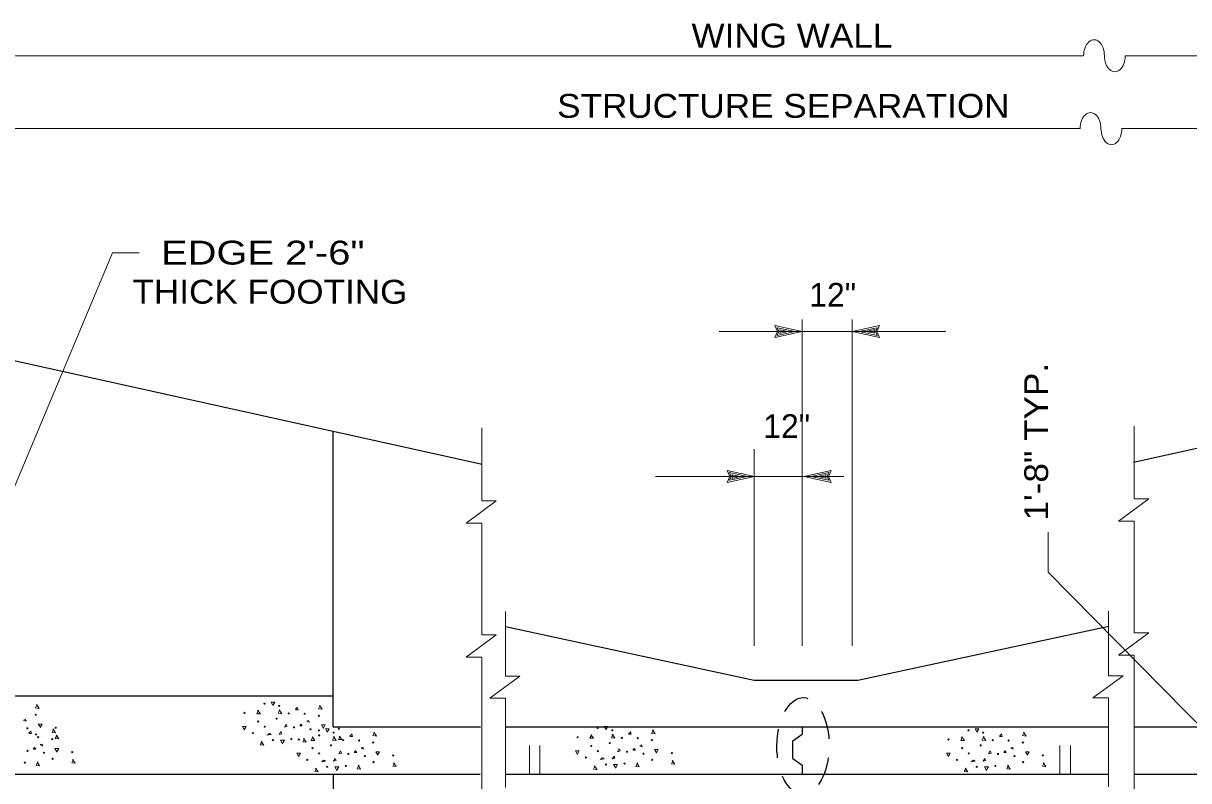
# Model space of a CAD drawing. Extents: x -22.3 to 19.7, y -11.8 to 18.2.
# Drawn here: x -0.65 to 5.45, y 2.35 to 6.32 of the extents above; entities that cross this region are included whole.
import ezdxf
from ezdxf.enums import TextEntityAlignment as Align

# ---------------------------------------------------------------- set-up
doc = ezdxf.new("R2010")
doc.units = 0
doc.header["$LTSCALE"] = 0.05
doc.linetypes.add('MEDIUM_DASHED', pattern=[4.5, 3, -1.5])
doc.layers.add('1', color=7, linetype='Continuous', lineweight=13)
doc.layers.add('2', color=7, linetype='Continuous', lineweight=13)

msp = doc.modelspace()

# ---------------------------------------------------------------- linework, layer by layer
at = {"layer": '1'}
for p, q in [((-1.02142, 6.14831), (4.89858, 6.14831)), ((5.11858, 6.14831), (7.85258, 6.14831)), ((-1.02142, 5.76631), (4.88358, 5.76631)), ((5.09858, 5.76631), (7.85258, 5.76631)), ((-0.18742, 5.11631), (-0.04642, 5.11631)), ((3.42658, 3.05731), (3.42658, 4.76731)), ((3.68758, 3.05731), (3.68758, 4.76731)), ((3.42658, 4.70331), (3.28258, 4.73431)), ((3.42658, 4.70331), (3.28258, 4.67231)), ((3.38958, 4.70331), (3.29558, 4.72331)), ((3.30458, 4.70331), (3.29558, 4.72331)), ((3.38958, 4.70331), (3.29558, 4.68331)), ((3.29558, 4.68331), (3.30458, 4.70331)), ((3.35358, 4.70331), (3.30858, 4.71231)), ((3.31258, 4.70331), (3.30858, 4.71231)), ((3.35358, 4.70331), (3.30858, 4.69331)), ((3.30858, 4.69331), (3.31258, 4.70331)), ((3.68758, 4.70331), (3.83158, 4.73431)), ((3.68758, 4.70331), (3.83158, 4.67231)), ((3.72458, 4.70331), (3.81858, 4.72331)), ((3.72458, 4.70331), (3.81858, 4.68331)), ((3.76058, 4.70331), (3.80558, 4.71331)), ((3.76058, 4.70331), (3.80558, 4.69431)), ((3.80558, 4.71331), (3.80158, 4.70331)), ((3.80158, 4.70331), (3.80558, 4.69431)), ((3.81858, 4.72331), (3.80958, 4.70331)), ((3.80958, 4.70331), (3.81858, 4.68331)), ((1.74758, 3.81631), (1.74758, 4.19831)), ((5.16558, 3.82631), (5.16558, 4.20831)), ((3.17458, 3.05731), (3.17458, 4.08731)), ((3.17658, 3.94431), (3.03258, 3.97531)), ((3.43458, 3.94431), (3.57858, 3.97531)), ((3.17658, 3.94431), (3.03258, 3.91331)), ((3.13958, 3.94431), (3.04558, 3.96431)), ((3.05458, 3.94431), (3.04558, 3.96431)), ((3.13958, 3.94431), (3.04558, 3.92431)), ((3.04558, 3.92431), (3.05458, 3.94431)), ((3.10358, 3.94431), (3.05858, 3.95331)), ((3.06258, 3.94431), (3.05858, 3.95331)), ((3.10358, 3.94431), (3.05858, 3.93431)), ((3.05858, 3.93431), (3.06258, 3.94431)), ((3.43458, 3.94431), (3.57858, 3.91331)), ((3.43458, 3.94431), (3.64458, 3.94431)), ((3.47158, 3.94431), (3.56558, 3.96431)), ((3.47158, 3.94431), (3.56558, 3.92431)), ((3.50758, 3.94431), (3.55258, 3.95431)), ((3.50758, 3.94431), (3.55258, 3.93531)), ((3.55258, 3.95431), (3.54858, 3.94431)), ((3.54858, 3.94431), (3.55258, 3.93531)), ((3.56558, 3.96431), (3.55658, 3.94431)), ((3.55658, 3.94431), (3.56558, 3.92431)), ((1.66558, 3.70031), (1.82358, 3.81631)), ((1.74758, 3.81631), (1.82358, 3.81631)), ((5.08358, 3.71031), (5.24158, 3.82631)), ((5.16558, 3.82631), (5.24158, 3.82631)), ((1.66558, 3.70031), (1.74758, 3.70031)), ((1.74758, 3.11431), (1.74758, 3.70031)), ((5.08358, 3.71031), (5.16558, 3.71031)), ((5.16558, 3.12431), (5.16558, 3.71031)), ((1.87158, 2.89831), (1.87158, 3.23731)), ((5.03158, 2.90031), (5.03158, 3.23931)), ((1.66558, 2.99831), (1.82358, 3.11431)), ((1.74758, 3.11431), (1.82358, 3.11431)), ((5.08358, 3.00831), (5.24158, 3.12431)), ((5.16558, 3.12431), (5.24158, 3.12431)), ((1.66558, 2.99831), (1.74758, 2.99831)), ((1.74758, 2.17131), (1.74758, 2.99831)), ((5.08358, 3.00831), (5.16558, 3.00831)), ((5.16558, 2.18131), (5.16558, 3.00831)), ((1.78958, 2.78231), (1.94758, 2.89831)), ((1.87158, 2.89831), (1.94758, 2.89831)), ((4.94958, 2.78431), (5.10758, 2.90031)), ((5.03158, 2.90031), (5.10758, 2.90031)), ((1.78958, 2.78231), (1.87158, 2.78231)), ((1.87158, 2.31531), (1.87158, 2.78231)), ((4.94958, 2.78431), (5.03158, 2.78431)), ((5.03158, 2.31731), (5.03158, 2.78431))]:
    msp.add_line(p, q, dxfattribs=at)
at = {"layer": '1', "lineweight": 25}
for p, q in [((-1.02142, 4.62231), (1.75058, 4.00831)), ((5.16258, 4.01931), (7.85058, 4.61031)), ((0.96858, 2.63231), (0.96858, 4.18131)), ((1.87258, 3.15731), (3.17458, 2.87631)), ((3.71858, 2.87631), (5.03258, 3.15931)), ((3.17458, 2.87631), (3.71858, 2.87631)), ((-1.02142, 2.79431), (0.96858, 2.79431)), ((0.96858, 2.63231), (1.74058, 2.63231)), ((1.87158, 2.63231), (5.03158, 2.63231)), ((3.42658, 2.62831), (3.42658, 2.59431)), ((5.16558, 2.63231), (5.90958, 2.63231)), ((3.37658, 2.46731), (3.42658, 2.43231)), ((-3.04142, 2.38431), (1.73958, 2.38431)), ((0.96858, 2.38431), (0.96858, 1.77531)), ((1.87158, 2.38431), (5.03158, 2.38431)), ((3.42658, 2.43231), (3.42658, 2.38331)), ((5.16558, 2.38431), (9.28558, 2.38431))]:
    msp.add_line(p, q, dxfattribs=at)
at = {"layer": '1', "linetype": 'MEDIUM_DASHED'}
for p, q in [((1.99858, 2.38431), (1.99858, 2.63231)), ((2.05158, 2.38431), (2.05158, 2.63231)), ((4.77658, 2.38431), (4.77658, 2.63231)), ((4.83158, 2.38431), (4.83158, 2.63231))]:
    msp.add_line(p, q, dxfattribs=at)
at = {"layer": '1'}
for points in [[(-0.18742, 5.11631), (-1.17742, 2.75631), (-1.15042, 2.90131)], [(2.99158, 4.70331), (3.42658, 4.70331), (3.68758, 4.70331), (4.17858, 4.70331)], [(3.28258, 4.67231), (3.29658, 4.70331), (3.28258, 4.73431)], [(3.83158, 4.73431), (3.81758, 4.70331), (3.83158, 4.67231)], [(3.03258, 3.91331), (3.04658, 3.94431), (3.03258, 3.97531)], [(3.57858, 3.97531), (3.56458, 3.94431), (3.57858, 3.91331)], [(2.65858, 3.94431), (3.17658, 3.94431), (3.43458, 3.94431)], [(5.55658, 2.58831), (4.71458, 3.44231), (4.71458, 3.65231)]]:
    msp.add_lwpolyline(points, dxfattribs=at)
at = {"layer": '1', "lineweight": 25}
msp.add_lwpolyline([(3.37658, 2.46731), (3.37658, 2.55931), (3.42658, 2.59431)], dxfattribs=at)
at = {"layer": '1'}
for centre, major_axis in [((4.95508, 6.14831), (0, -0.084)), ((5.06408, 6.14831), (0, 0.084)), ((4.93708, 5.76631), (0, -0.084)), ((5.04608, 5.76631), (0, 0.084))]:
    msp.add_ellipse(centre, major_axis=major_axis, ratio=0.648782, start_param=1.5707963, end_param=4.712389, dxfattribs=at)
at = {"layer": '1', "linetype": 'MEDIUM_DASHED', "lineweight": 25}
msp.add_ellipse((3.43058, 2.53231), major_axis=(-0.002, -0.253), ratio=0.540911, dxfattribs=at)
at = {"layer": '2'}
for p, q in [((0.77158, 2.72431), (0.78158, 2.73331)), ((-0.62442, 2.60131), (-0.61442, 2.61031)), ((1.05658, 2.58431), (1.06658, 2.59331)), ((2.51658, 2.59631), (2.52658, 2.60531)), ((4.45958, 2.58431), (4.46958, 2.59331))]:
    msp.add_line(p, q, dxfattribs=at)
for points in [[(-0.58142, 2.74931), (-0.59042, 2.73131), (-0.57142, 2.72931), (-0.58542, 2.74931)], [(0.65358, 2.74631), (0.64458, 2.76231), (0.66358, 2.76231), (0.65358, 2.74431)], [(0.57858, 2.71931), (0.56958, 2.70131), (0.58858, 2.70031), (0.57358, 2.71931)], [(0.69058, 2.72131), (0.68158, 2.70331), (0.69958, 2.70131), (0.68658, 2.72131)], [(0.78158, 2.73531), (0.78558, 2.72131), (0.77158, 2.72131)], [(0.90158, 2.74431), (0.89258, 2.72631), (0.91158, 2.72431), (0.89758, 2.74431)], [(-0.65242, 2.66731), (-0.64342, 2.67031), (-0.63942, 2.66131), (-0.65242, 2.66531)], [(-0.56642, 2.63231), (-0.57542, 2.64731), (-0.55542, 2.64731), (-0.56642, 2.62831)], [(0.50258, 2.61931), (0.49358, 2.63431), (0.51358, 2.63431), (0.50258, 2.61631)], [(0.79458, 2.63831), (0.80058, 2.64731), (0.80758, 2.63831), (0.79658, 2.63831)], [(0.83058, 2.66231), (0.83958, 2.66531), (0.84358, 2.65631), (0.83058, 2.66031)], [(0.91658, 2.62731), (0.90758, 2.64231), (0.92758, 2.64231), (0.91658, 2.62331)], [(2.39858, 2.61831), (2.38958, 2.63431), (2.40858, 2.63431), (2.39858, 2.61631)], [(-0.61442, 2.61231), (-0.61042, 2.59831), (-0.62442, 2.59831)], [(-0.49442, 2.62131), (-0.50342, 2.60331), (-0.48442, 2.60131), (-0.49842, 2.62131)], [(-0.47742, 2.58931), (-0.48642, 2.57131), (-0.46842, 2.57031), (-0.48242, 2.58931)], [(0.62658, 2.59231), (0.63558, 2.59831), (0.64458, 2.59231), (0.62258, 2.58931)], [(0.81858, 2.57131), (0.80958, 2.55331), (0.82758, 2.55131), (0.81458, 2.57131)], [(0.86358, 2.57931), (0.85458, 2.56131), (0.87358, 2.56031), (0.85858, 2.57931)], [(0.93858, 2.60631), (0.92958, 2.62231), (0.94858, 2.62231), (0.93858, 2.60431)], [(0.97558, 2.58131), (0.96658, 2.56331), (0.98458, 2.56131), (0.97158, 2.58131)], [(1.00558, 2.58431), (0.99658, 2.56631), (1.01458, 2.56531), (1.00058, 2.58431)], [(1.06658, 2.59531), (1.07058, 2.58131), (1.05658, 2.58131)], [(1.18658, 2.60431), (1.17758, 2.58631), (1.19658, 2.58431), (1.18258, 2.60431)], [(2.32358, 2.59131), (2.31458, 2.57331), (2.33358, 2.57231), (2.31858, 2.59131)], [(2.43558, 2.59331), (2.42658, 2.57531), (2.44458, 2.57331), (2.43158, 2.59331)], [(2.52658, 2.60731), (2.53058, 2.59331), (2.51658, 2.59331)], [(2.64658, 2.61631), (2.63758, 2.59831), (2.65658, 2.59631), (2.64258, 2.61631)], [(4.26658, 2.57931), (4.25758, 2.56131), (4.27658, 2.56031), (4.26158, 2.57931)], [(4.34158, 2.60631), (4.33258, 2.62231), (4.35158, 2.62231), (4.34158, 2.60431)], [(4.37858, 2.58131), (4.36958, 2.56331), (4.38758, 2.56131), (4.37458, 2.58131)], [(4.46958, 2.59531), (4.47358, 2.58131), (4.45958, 2.58131)], [(4.58958, 2.60431), (4.58058, 2.58631), (4.59958, 2.58431), (4.58558, 2.60431)], [(-0.60142, 2.51531), (-0.59542, 2.52431), (-0.58842, 2.51531), (-0.59942, 2.51531)], [(-0.56542, 2.53931), (-0.55642, 2.54231), (-0.55242, 2.53331), (-0.56542, 2.53731)], [(-0.47942, 2.50431), (-0.48842, 2.51931), (-0.46842, 2.51931), (-0.47942, 2.50031)], [(0.59658, 2.55631), (0.58758, 2.53831), (0.60658, 2.53631), (0.59158, 2.55631)], [(0.70258, 2.54731), (0.69358, 2.56231), (0.71358, 2.56231), (0.70258, 2.54331)], [(1.07958, 2.49831), (1.08558, 2.50731), (1.09258, 2.49831), (1.08158, 2.49831)], [(1.11558, 2.52231), (1.12458, 2.52531), (1.12858, 2.51631), (1.11558, 2.52031)], [(2.24758, 2.49131), (2.23858, 2.50631), (2.25858, 2.50631), (2.24758, 2.48831)], [(2.53958, 2.51031), (2.54558, 2.51931), (2.55258, 2.51031), (2.54158, 2.51031)], [(2.57558, 2.53431), (2.58458, 2.53731), (2.58858, 2.52831), (2.57558, 2.53231)], [(2.66158, 2.49931), (2.65258, 2.51431), (2.67258, 2.51431), (2.66158, 2.49531)], [(4.48258, 2.49831), (4.48858, 2.50731), (4.49558, 2.49831), (4.48458, 2.49831)], [(4.51858, 2.52231), (4.52758, 2.52531), (4.53158, 2.51631), (4.51858, 2.52031)], [(-0.57742, 2.44831), (-0.58642, 2.43031), (-0.56842, 2.42831), (-0.58142, 2.44831)], [(-0.39042, 2.46131), (-0.39942, 2.44331), (-0.38142, 2.44231), (-0.39542, 2.46131)], [(0.78758, 2.47931), (0.77858, 2.49431), (0.79858, 2.49431), (0.78758, 2.47631)], [(0.91158, 2.45231), (0.92058, 2.45831), (0.92958, 2.45231), (0.90758, 2.44931)], [(1.20158, 2.48731), (1.19258, 2.50231), (1.21258, 2.50231), (1.20158, 2.48331)], [(1.29058, 2.44431), (1.28158, 2.42631), (1.29958, 2.42531), (1.28558, 2.44431)], [(2.37158, 2.46431), (2.38058, 2.47031), (2.38958, 2.46431), (2.36758, 2.46131)], [(2.56358, 2.44331), (2.55458, 2.42531), (2.57258, 2.42331), (2.55958, 2.44331)], [(2.75058, 2.45631), (2.74158, 2.43831), (2.75958, 2.43731), (2.74558, 2.45631)], [(4.19058, 2.47931), (4.18158, 2.49431), (4.20158, 2.49431), (4.19058, 2.47631)], [(4.31458, 2.45231), (4.32358, 2.45831), (4.33258, 2.45231), (4.31058, 2.44931)], [(4.60458, 2.48731), (4.59558, 2.50231), (4.61558, 2.50231), (4.60458, 2.48331)], [(4.69358, 2.44431), (4.68458, 2.42631), (4.70258, 2.42531), (4.68858, 2.44431)], [(0.88158, 2.41631), (0.87258, 2.39831), (0.89158, 2.39631), (0.87658, 2.41631)], [(0.98758, 2.40731), (0.97858, 2.42231), (0.99858, 2.42231), (0.98758, 2.40331)], [(1.10358, 2.43131), (1.09458, 2.41331), (1.11258, 2.41131), (1.09958, 2.43131)], [(2.34158, 2.42831), (2.33258, 2.41031), (2.35158, 2.40831), (2.33658, 2.42831)], [(2.44758, 2.41931), (2.43858, 2.43431), (2.45858, 2.43431), (2.44758, 2.41531)], [(4.28458, 2.41631), (4.27558, 2.39831), (4.29458, 2.39631), (4.27958, 2.41631)], [(4.39058, 2.40731), (4.38158, 2.42231), (4.40158, 2.42231), (4.39058, 2.40331)], [(4.50658, 2.43131), (4.49758, 2.41331), (4.51558, 2.41131), (4.50258, 2.43131)]]:
    msp.add_lwpolyline(points, dxfattribs=at)
for points in [[(0.71358, 2.63031), (0.72258, 2.64731), (0.72758, 2.63531)], [(0.68658, 2.59231), (0.69558, 2.60731), (0.69958, 2.59631)], [(0.99858, 2.49031), (1.00758, 2.50731), (1.01258, 2.49531)], [(2.45858, 2.50231), (2.46758, 2.51931), (2.47258, 2.50731)], [(4.40158, 2.49031), (4.41058, 2.50731), (4.41558, 2.49531)], [(0.97158, 2.45231), (0.98058, 2.46731), (0.98458, 2.45631)], [(2.43158, 2.46431), (2.44058, 2.47931), (2.44458, 2.46831)], [(4.37458, 2.45231), (4.38358, 2.46731), (4.38758, 2.45631)]]:
    msp.add_lwpolyline(points, close=True, dxfattribs=at)
for centre in [(0.60953, 2.75414), (-0.58907, 2.69569), (0.50468, 2.70599), (0.68648, 2.74199), (0.73643, 2.70284), (0.81968, 2.70104), (0.89393, 2.69069), (-0.63272, 2.62459), (-0.48422, 2.62774), (0.57623, 2.66054), (0.61088, 2.63309), (0.67298, 2.67539), (0.76388, 2.62994), (0.99878, 2.62274), (2.35453, 2.62614), (-0.58727, 2.59264), (-0.57632, 2.57804), (-0.50207, 2.56769), (0.54878, 2.59979), (0.65318, 2.56334), (0.75038, 2.56784), (0.78968, 2.56599), (0.85028, 2.61959), (0.89453, 2.61414), (0.89573, 2.58764), (0.97148, 2.60199), (1.02143, 2.56284), (2.24968, 2.57799), (2.43148, 2.61399), (2.48143, 2.57484), (2.56468, 2.57304), (2.63893, 2.56269), (4.19268, 2.56599), (4.29753, 2.61414), (4.37448, 2.60199), (4.42443, 2.56284), (-0.63212, 2.50694), (0.86123, 2.52054), (0.95798, 2.53539), (1.10468, 2.56104), (1.17893, 2.55069), (2.32123, 2.53254), (2.35588, 2.50509), (2.41798, 2.54739), (2.50888, 2.50194), (4.26423, 2.52054), (4.36098, 2.53539), (4.50768, 2.56104), (4.58193, 2.55069), (-0.64562, 2.44484), (-0.54572, 2.49659), (-0.50027, 2.46464), (-0.39722, 2.49974), (0.83378, 2.45979), (0.89588, 2.49309), (1.04888, 2.48994), (1.13528, 2.47959), (1.18073, 2.44764), (1.28378, 2.48274), (2.29378, 2.47179), (2.49538, 2.43984), (2.59528, 2.49159), (2.64073, 2.45964), (2.74378, 2.49474), (4.23678, 2.45979), (4.29888, 2.49309), (4.45188, 2.48994), (4.53828, 2.47959), (4.58373, 2.44764), (4.68678, 2.48274), (0.93818, 2.42334), (1.03538, 2.42784), (2.39818, 2.43534), (4.34118, 2.42334), (4.43838, 2.42784)]:
    msp.add_circle(centre, 0.00293, dxfattribs=at)

# ---------------------------------------------------------------- texts
at = {"layer": '1', "width": 1.1}
for s, p in [('WING WALL', (3.37258, 6.19131)), ('STRUCTURE SEPARATION', (3.32758, 5.82331)), ('THICK FOOTING', (0.63808, 4.84931))]:
    msp.add_text(s, height=0.125, dxfattribs=at).set_placement(p, align=Align.CENTER)
at = {"layer": '1', "width": 1.25}
msp.add_text('EDGE 2\'-6"', height=0.125, dxfattribs=at).set_placement((0.06758, 5.05431))
at = {"layer": '1'}
for p in [(3.58608, 4.83331), (3.34508, 4.14531)]:
    msp.add_text('12"', height=0.125, dxfattribs=at).set_placement(p, align=Align.CENTER)
at = {"layer": '1', "width": 1.1}
msp.add_text('1\'-8" TYP.', height=0.125, rotation=90, dxfattribs=at).set_placement((4.71458, 3.71331))

doc.saveas('drawing.dxf')
